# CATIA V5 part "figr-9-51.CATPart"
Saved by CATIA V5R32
Part number: Part1
Bounding box of the stored display mesh (mm): x -121 to 121, y -90 to 90, z -40 to 40
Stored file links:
  D:\PROJECTS\Project 2022\CATIA V5 6R 2022\Resources\Part Files\c09_catia_v5_6r2022_prt\c09_catia_v5_6r2022_prt\figr-9-51.CATPart
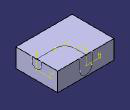
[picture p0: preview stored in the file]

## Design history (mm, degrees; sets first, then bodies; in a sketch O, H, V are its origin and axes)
Body1 (main body)
  Sketch1 on yz-plane, origin (0, 0, 0), H (0, 1, 0), V (0, 0, 1)
    line L1 (-90, 40) -> (90, 40)
    line L2 (90, 40) -> (90, -40)
    line L3 (90, -40) -> (-90, -40)
    line L4 (-90, -40) -> (-90, 40)
    axis line L5 (90, -40) -> (-90, 40)
    horizontal: L1 H, L3 H
    vertical: L2 V, L4 V
    midpoint: O L5
  Pad1: profile Sketch1, direction (1, 0, 0), length 121, mirrored extent
  Sketch2 on face of Pad1, origin (0, 0, 40), H (1, 0, 0), V (0, 1, 0)
    point P1 (121, 0)
    line L1 (121, 0) -> (40.984, 0)
    arc A1 centre (40.984, 40.984) radius 40.984 from (40.984, 0) to (0, 40.984) cw
    line L2 (0, 40.984) -> (0, 90)
    point P5 (0, 90)
    reference projected line E1 (121, 20) -> (121, -20) from edge of Sketch4
    reference projected line E2 (-25.9516, 90) -> (25.9516, 90) from edge of Sketch3
    coincidence: P1 H, P1 E1, P5 E2
    horizontal: L1 H
    tangency: A1 L1, L2 A1
    vertical: L2 V
  Sketch3 on face of Pad1, origin (0, 90, 0), H (-1, 0, 0), V (0, 0, 1)
    line L1 (-25.9516, 40) -> (-25.9516, -8.0968)
    arc A1 centre (0, -8.0968) radius 25.9516 from (-25.9516, -8.0968) to (25.9516, -8.0968) ccw
    point P3 (0, -8.0968)
    line L2 (25.9516, -8.0968) -> (25.9516, 40)
    line L3 (25.9516, 40) -> (-25.9516, 40)
    reference projected line E1 (121, 40) -> (-121, 40) from edge [face of Pad1 | face of Pad1]
    vertical: L1 V, L2 V
    tangency: A1 L1, L2 A1
    horizontal: L3 H
    coincidence: P3 V, L3 E1
  Sketch4 on face of Pad1, origin (121, 0, 0), H (0, 1, 0), V (0, 0, 1)
    line L1 (-20, 40) -> (-20, 21.9917)
    arc A1 centre (0, 21.9917) radius 20 from (-20, 21.9917) to (20, 21.9917) ccw
    point P3 (0, 21.9917)
    line L2 (20, 21.9917) -> (20, 40)
    line L3 (20, 40) -> (-20, 40)
    reference projected line E1 (90, 40) -> (-90, 40) from edge [face of Pad1 | face of Pad1]
    vertical: L1 V, L2 V
    tangency: A1 L1, L2 A1
    horizontal: L3 H
    coincidence: P3 V, L3 E1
